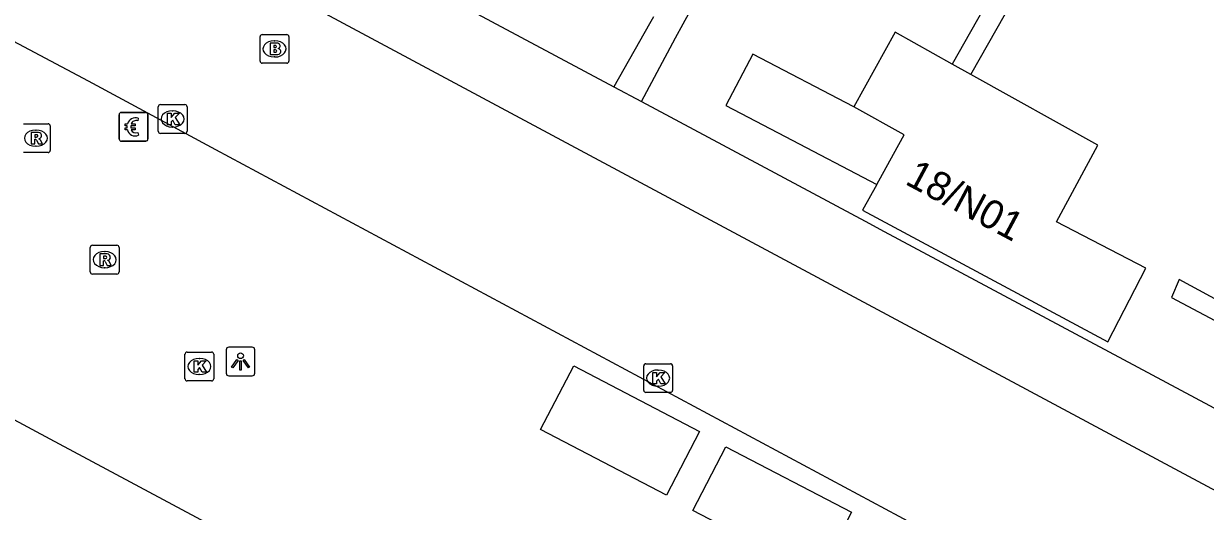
# Model space of a CAD drawing. Extents: x 159489 to 160304, y 383826 to 384530.
# Drawn here: x 160083.44 to 160124.51, y 384041.9 to 384058.85 of the extents above; entities that cross this region are included whole.
import ezdxf

# ---------------------------------------------------------------- set-up
doc = ezdxf.new("R2010")
doc.units = 0
for name, color, linetype in [('IMGEO_Betaalautomaat', 7, 'Continuous'), ('IMGEO_Brandkraan', 7, 'Continuous'), ('IMGEO_Fietspad_gesloten', 7, 'Continuous'), ('IMGEO_Haag', 7, 'Continuous'), ('IMGEO_Kolk', 7, 'Continuous'), ('IMGEO_Lichtpunt', 7, 'Continuous'), ('IMGEO_Pand', 7, 'Continuous'), ('IMGEO_Pand_nummerreeks', 7, 'Continuous'), ('IMGEO_Parkeervlak_open', 7, 'Continuous'), ('IMGEO_Rijbaan_lokaal_open', 7, 'Continuous'), ('IMGEO_Rioolput', 7, 'Continuous'), ('IMGEO_Voetpad_op_trap', 7, 'Continuous'), ('IMGEO_Voetpad_open', 7, 'Continuous')]:
    doc.layers.add(name, color=color, linetype=linetype)

msp = doc.modelspace()

# ---------------------------------------------------------------- linework, layer by layer
at = {"layer": 'IMGEO_Betaalautomaat'}
for p, q in [((160086.762, 384054.84), (160086.762, 384055.681)), ((160086.762, 384055.681), (160086.762, 384054.84)), ((160086.837, 384055.764), (160087.678, 384055.764)), ((160087.678, 384055.764), (160086.837, 384055.764)), ((160087.761, 384055.69), (160087.761, 384054.849)), ((160087.761, 384054.849), (160087.761, 384055.69)), ((160087.045, 384055.228), (160087.045, 384055.296)), ((160087.166, 384055.296), (160087.166, 384055.228)), ((160087.424, 384055.569), (160087.407, 384055.469)), ((160087.411, 384055.063), (160087.433, 384054.976)), ((160087.687, 384054.765), (160086.846, 384054.765)), ((160086.846, 384054.765), (160087.687, 384054.765))]:
    msp.add_line(p, q, dxfattribs=at)
for points in [[(160087.045, 384055.296), (160086.976, 384055.296), (160086.976, 384055.365), (160087.055, 384055.365)], [(160087.05, 384055.159), (160086.976, 384055.159), (160086.976, 384055.228), (160087.045, 384055.228)], [(160087.177, 384055.365), (160087.324, 384055.365), (160087.324, 384055.296), (160087.166, 384055.296)], [(160087.166, 384055.228), (160087.324, 384055.228), (160087.324, 384055.159), (160087.18, 384055.159)]]:
    msp.add_lwpolyline(points, dxfattribs=at)
for centre, radius, start, end in [((160086.84, 384055.687), 0.0779, 92.4484, 184.2845), ((160086.84, 384055.687), 0.0779, 92.4484, 184.2845), ((160087.684, 384055.687), 0.0779, 2.4484, 94.2845), ((160087.684, 384055.687), 0.0779, 2.4484, 94.2845), ((160087.338, 384055.289), 0.293, 73.014, 165.0139), ((160087.344, 384055.302), 0.179, 69.3236, 159.5683), ((160086.84, 384054.843), 0.0779, 182.4484, 274.2845), ((160086.84, 384054.843), 0.0779, 182.4484, 274.2845), ((160087.311, 384055.214), 0.267, 191.8096, 297.0389), ((160087.344, 384055.229), 0.179, 202.7625, 291.8693), ((160087.684, 384054.843), 0.0779, 272.4484, 4.2845), ((160087.684, 384054.843), 0.0779, 272.4484, 4.2845)]:
    msp.add_arc(centre, radius, start, end, dxfattribs=at)
at = {"layer": 'IMGEO_Brandkraan'}
for p, q in [((160091.661, 384057.545), (160091.661, 384058.397)), ((160091.736, 384058.471), (160092.588, 384058.471)), ((160092.149, 384058.251), (160092.174, 384058.251)), ((160092.662, 384058.397), (160092.662, 384057.545)), ((160092.172, 384057.691), (160092.147, 384057.691)), ((160092.588, 384057.471), (160091.736, 384057.471))]:
    msp.add_line(p, q, dxfattribs=at)
for points in [[(160091.661, 384057.545), (160091.661, 384058.397)], [(160091.736, 384058.471), (160092.588, 384058.471)], [(160092.009, 384058.171), (160092.009, 384057.771), (160092.222, 384057.771)], [(160092.24, 384058.171), (160092.009, 384058.171)], [(160092.188, 384058.09), (160092.134, 384058.09), (160092.134, 384058.014)], [(160092.662, 384058.397), (160092.662, 384057.545)], [(160092.134, 384058.014), (160092.187, 384058.014)], [(160092.196, 384057.938), (160092.134, 384057.938), (160092.134, 384057.857)], [(160092.134, 384057.857), (160092.196, 384057.857)], [(160092.588, 384057.471), (160091.736, 384057.471)]]:
    msp.add_lwpolyline(points, dxfattribs=at)
for centre, radius, start, end in [((160091.738, 384058.395), 0.0765, 91.552, 178.448), ((160091.738, 384058.395), 0.0765, 91.552, 178.448), ((160092.189, 384058.052), 0.0379, 267.8285, 90.9355), ((160092.244, 384058.026), 0.145, 59.4692, 91.5367), ((160092.269, 384058.073), 0.0922, 285.5137, 58.1501), ((160092.586, 384058.395), 0.0765, 1.552, 88.448), ((160092.586, 384058.395), 0.0765, 1.552, 88.448), ((160092.197, 384057.897), 0.0404, 269.8759, 90.5077), ((160092.228, 384058.022), 0.251, 268.6676, 293.5347), ((160092.274, 384057.881), 0.105, 301.3115, 78.989), ((160091.738, 384057.547), 0.0765, 181.552, 268.448), ((160091.738, 384057.547), 0.0765, 181.552, 268.448), ((160092.586, 384057.547), 0.0765, 271.552, 358.448), ((160092.586, 384057.547), 0.0765, 271.552, 358.448)]:
    msp.add_arc(centre, radius, start, end, dxfattribs=at)
for centre, major_axis, ratio, start_param, end_param in [((160092.148, 384057.971), (-0.387, 0.002), 0.722429, 4.712389, 7.853982), ((160092.173, 384057.971), (-0.39, 0.002), 0.717154, 1.570796, 4.712389)]:
    msp.add_ellipse(centre, major_axis=major_axis, ratio=ratio, start_param=start_param, end_param=end_param, dxfattribs=at)
at = {"layer": 'IMGEO_Fietspad_gesloten'}
msp.add_arc((160615.404, 384561.74), 696.522, 225.116755, 226.921789, dxfattribs=at)
at = {"layer": 'IMGEO_Haag'}
msp.add_lwpolyline([(160123.601, 384049.959), (160123.333, 384049.339), (160129.56, 384046.03), (160129.855, 384046.571), (160123.601, 384049.959)], dxfattribs=at)
at = {"layer": 'IMGEO_Kolk'}
for p, q in [((160088.196, 384056.036), (160089.048, 384056.036)), ((160088.121, 384055.11), (160088.121, 384055.962)), ((160088.609, 384055.816), (160088.634, 384055.816)), ((160089.122, 384055.962), (160089.122, 384055.11)), ((160088.632, 384055.256), (160088.607, 384055.256)), ((160089.048, 384055.036), (160088.196, 384055.036)), ((160089.126, 384047.437), (160089.978, 384047.437)), ((160089.051, 384046.511), (160089.051, 384047.363)), ((160089.539, 384047.217), (160089.564, 384047.217)), ((160090.052, 384047.363), (160090.052, 384046.511)), ((160105.07, 384047.034), (160105.922, 384047.034)), ((160089.562, 384046.657), (160089.537, 384046.657)), ((160104.995, 384046.108), (160104.995, 384046.96)), ((160105.483, 384046.814), (160105.508, 384046.814)), ((160105.996, 384046.96), (160105.996, 384046.108)), ((160089.978, 384046.437), (160089.126, 384046.437)), ((160105.506, 384046.254), (160105.481, 384046.254)), ((160105.922, 384046.034), (160105.07, 384046.034))]:
    msp.add_line(p, q, dxfattribs=at)
for points in [[(160088.196, 384056.036), (160089.048, 384056.036)], [(160088.121, 384055.11), (160088.121, 384055.962)], [(160088.442, 384055.736), (160088.565, 384055.736), (160088.565, 384055.585), (160088.695, 384055.736), (160088.859, 384055.736), (160088.713, 384055.585), (160088.866, 384055.336), (160088.714, 384055.336), (160088.629, 384055.5), (160088.565, 384055.433), (160088.565, 384055.336), (160088.442, 384055.336), (160088.442, 384055.736)], [(160089.122, 384055.962), (160089.122, 384055.11)], [(160089.048, 384055.036), (160088.196, 384055.036)], [(160089.126, 384047.437), (160089.978, 384047.437)], [(160089.051, 384046.511), (160089.051, 384047.363)], [(160089.372, 384047.137), (160089.495, 384047.137), (160089.495, 384046.986), (160089.625, 384047.137), (160089.789, 384047.137), (160089.643, 384046.986), (160089.796, 384046.737), (160089.644, 384046.737), (160089.559, 384046.901), (160089.495, 384046.834), (160089.495, 384046.737), (160089.372, 384046.737), (160089.372, 384047.137)], [(160090.052, 384047.363), (160090.052, 384046.511)], [(160105.07, 384047.034), (160105.922, 384047.034)], [(160104.995, 384046.108), (160104.995, 384046.96)], [(160105.316, 384046.734), (160105.439, 384046.734), (160105.439, 384046.583), (160105.569, 384046.734), (160105.733, 384046.734), (160105.587, 384046.583), (160105.74, 384046.334), (160105.588, 384046.334), (160105.503, 384046.498), (160105.439, 384046.431), (160105.439, 384046.334), (160105.316, 384046.334), (160105.316, 384046.734)], [(160105.996, 384046.96), (160105.996, 384046.108)], [(160089.978, 384046.437), (160089.126, 384046.437)], [(160105.922, 384046.034), (160105.07, 384046.034)]]:
    msp.add_lwpolyline(points, dxfattribs=at)
for centre, start, end in [((160088.198, 384055.96), 91.552, 178.448), ((160088.198, 384055.96), 91.552, 178.448), ((160089.046, 384055.96), 1.552, 88.448), ((160089.046, 384055.96), 1.552, 88.448), ((160088.198, 384055.112), 181.552, 268.448), ((160088.198, 384055.112), 181.552, 268.448), ((160089.046, 384055.112), 271.552, 358.448), ((160089.046, 384055.112), 271.552, 358.448), ((160089.128, 384047.361), 91.552, 178.448), ((160089.128, 384047.361), 91.552, 178.448), ((160089.976, 384047.361), 1.552, 88.448), ((160089.976, 384047.361), 1.552, 88.448), ((160105.072, 384046.958), 91.552, 178.448), ((160105.072, 384046.958), 91.552, 178.448), ((160105.92, 384046.958), 1.552, 88.448), ((160105.92, 384046.958), 1.552, 88.448), ((160089.128, 384046.513), 181.552, 268.448), ((160089.128, 384046.513), 181.552, 268.448), ((160089.976, 384046.513), 271.552, 358.448), ((160089.976, 384046.513), 271.552, 358.448), ((160105.072, 384046.11), 181.552, 268.448), ((160105.072, 384046.11), 181.552, 268.448), ((160105.92, 384046.11), 271.552, 358.448), ((160105.92, 384046.11), 271.552, 358.448)]:
    msp.add_arc(centre, 0.0765, start, end, dxfattribs=at)
for centre, major_axis, ratio, start_param, end_param in [((160088.608, 384055.536), (-0.387, 0.002), 0.722429, 4.712389, 7.853982), ((160088.633, 384055.536), (-0.39, 0.002), 0.717154, 1.570796, 4.712389), ((160089.538, 384046.937), (-0.387, 0.002), 0.722429, 4.712389, 7.853982), ((160089.563, 384046.937), (-0.39, 0.002), 0.717154, 1.570796, 4.712389), ((160105.482, 384046.534), (-0.387, 0.002), 0.722429, 4.712389, 7.853982), ((160105.507, 384046.534), (-0.39, 0.002), 0.717154, 1.570796, 4.712389)]:
    msp.add_ellipse(centre, major_axis=major_axis, ratio=ratio, start_param=start_param, end_param=end_param, dxfattribs=at)
at = {"layer": 'IMGEO_Lichtpunt'}
for p, q in [((160090.483, 384047.514), (160090.483, 384046.707)), ((160090.483, 384047.514), (160090.483, 384046.707)), ((160091.385, 384047.609), (160090.577, 384047.609)), ((160091.385, 384047.609), (160090.577, 384047.609)), ((160091.479, 384046.707), (160091.479, 384047.514)), ((160091.479, 384046.707), (160091.479, 384047.514)), ((160090.577, 384046.613), (160091.385, 384046.613)), ((160090.577, 384046.613), (160091.385, 384046.613))]:
    msp.add_line(p, q, dxfattribs=at)
for points in [[(160090.857, 384047.178), (160090.896, 384047.15), (160090.708, 384046.888), (160090.67, 384046.915), (160090.857, 384047.178)], [(160090.959, 384047.13), (160091.006, 384047.13), (160091.006, 384046.808), (160090.959, 384046.808), (160090.959, 384047.13)], [(160091.069, 384047.15), (160091.107, 384047.177), (160091.294, 384046.915), (160091.255, 384046.887), (160091.069, 384047.15)]]:
    msp.add_lwpolyline(points, dxfattribs=at)
msp.add_circle((160090.982, 384047.312), 0.0994, dxfattribs=at)
for centre, start, end in [((160090.577, 384047.514), 90, 180), ((160090.577, 384047.514), 90, 180), ((160091.385, 384047.514), 0, 90), ((160091.385, 384047.514), 0, 90), ((160090.577, 384046.707), 180, 270), ((160090.577, 384046.707), 180, 270), ((160091.385, 384046.707), 270, 0), ((160091.385, 384046.707), 270, 360)]:
    msp.add_arc(centre, 0.0946, start, end, dxfattribs=at)
at = {"layer": 'IMGEO_Pand'}
for points in [[(160073.755, 384058.611), (160074.776, 384058.065), (160074.653, 384057.835), (160074.445, 384057.447), (160075.061, 384057.116), (160072.374, 384052.088), (160071.43, 384052.592), (160070.91, 384051.621), (160077.333, 384048.184), (160084.358, 384044.424), (160120.106, 384025.292)], [(160115.714, 384057.446), (160113.731, 384058.549), (160112.297, 384055.958)], [(160116.369, 384057.081), (160115.714, 384057.446)], [(160113.091, 384053.263), (160112.594, 384052.365), (160121.127, 384047.794), (160122.451, 384050.357), (160119.343, 384051.962), (160120.775, 384054.629), (160116.369, 384057.081)], [(160113.091, 384053.263), (160113.67, 384054.308), (160114.047, 384054.99), (160112.297, 384055.958)]]:
    msp.add_lwpolyline(points, dxfattribs=at)
at = {"layer": 'IMGEO_Parkeervlak_open'}
for points in [[(160098.684, 384059.472), (160103.951, 384056.655)], [(160104.914, 384056.141), (160112.692, 384051.981), (160113.354, 384051.627), (160128.32, 384043.623)]]:
    msp.add_lwpolyline(points, dxfattribs=at)
at = {"layer": 'IMGEO_Rijbaan_lokaal_open'}
for points in [[(160171.245, 384010.937), (160125.267, 384035.607), (160090.12, 384054.464), (160085.703, 384056.846), (160076.546, 384061.719), (160076.371, 384061.813)], [(160131.209, 384039.227), (160093.439, 384059.454)]]:
    msp.add_lwpolyline(points, dxfattribs=at)
at = {"layer": 'IMGEO_Rioolput'}
for p, q in [((160083.443, 384055.369), (160084.295, 384055.369)), ((160084.369, 384055.295), (160084.369, 384054.443)), ((160083.856, 384055.149), (160083.881, 384055.149)), ((160083.879, 384054.589), (160083.854, 384054.589)), ((160084.295, 384054.369), (160083.443, 384054.369)), ((160085.835, 384051.149), (160086.687, 384051.149)), ((160085.76, 384050.223), (160085.76, 384051.075)), ((160086.248, 384050.929), (160086.273, 384050.929)), ((160086.761, 384051.075), (160086.761, 384050.223)), ((160086.271, 384050.369), (160086.246, 384050.369)), ((160086.687, 384050.149), (160085.835, 384050.149))]:
    msp.add_line(p, q, dxfattribs=at)
for points in [[(160083.443, 384055.369), (160084.295, 384055.369)], [(160084.369, 384055.295), (160084.369, 384054.443)], [(160083.957, 384055.067), (160083.705, 384055.069), (160083.705, 384054.669)], [(160083.705, 384054.669), (160083.829, 384054.669), (160083.829, 384054.831), (160083.84, 384054.831)], [(160083.883, 384054.988), (160083.829, 384054.988), (160083.829, 384054.907)], [(160083.829, 384054.907), (160083.881, 384054.907)], [(160083.887, 384054.802), (160083.958, 384054.669), (160084.098, 384054.669), (160084.033, 384054.795)], [(160084.295, 384054.369), (160083.443, 384054.369)], [(160085.835, 384051.149), (160086.687, 384051.149)], [(160085.76, 384050.223), (160085.76, 384051.075)], [(160086.349, 384050.847), (160086.097, 384050.849), (160086.097, 384050.449)], [(160086.275, 384050.768), (160086.221, 384050.768), (160086.221, 384050.687)], [(160086.221, 384050.687), (160086.273, 384050.687)], [(160086.761, 384051.075), (160086.761, 384050.223)], [(160086.097, 384050.449), (160086.221, 384050.449), (160086.221, 384050.611), (160086.232, 384050.611)], [(160086.279, 384050.582), (160086.35, 384050.449), (160086.49, 384050.449), (160086.425, 384050.575)], [(160086.687, 384050.149), (160085.835, 384050.149)]]:
    msp.add_lwpolyline(points, dxfattribs=at)
for centre, radius, start, end in [((160084.293, 384055.293), 0.0765, 1.552, 88.448), ((160084.293, 384055.293), 0.0765, 1.552, 88.448), ((160083.839, 384054.778), 0.0533, 26.0293, 88.6989), ((160083.865, 384055.096), 0.19, 274.7715, 282.9687), ((160083.889, 384054.892), 0.0964, 77.0061, 93.1865), ((160083.903, 384054.949), 0.0378, 276.6634, 79.6772), ((160083.956, 384054.957), 0.109, 350.3612, 89.416), ((160083.954, 384054.957), 0.112, 277.5842, 350.9817), ((160083.938, 384054.742), 0.108, 29.5134, 73.7905), ((160084.293, 384054.445), 0.0765, 271.552, 358.448), ((160084.293, 384054.445), 0.0765, 271.552, 358.448), ((160085.837, 384051.073), 0.0765, 91.552, 178.448), ((160085.837, 384051.073), 0.0765, 91.552, 178.448), ((160086.685, 384051.073), 0.0765, 1.552, 88.448), ((160086.685, 384051.073), 0.0765, 1.552, 88.448), ((160086.257, 384050.876), 0.19, 274.7715, 282.9687), ((160086.281, 384050.672), 0.0964, 77.0061, 93.1865), ((160086.295, 384050.729), 0.0378, 276.6634, 79.6772), ((160086.348, 384050.737), 0.109, 350.3612, 89.416), ((160086.346, 384050.737), 0.112, 277.5842, 350.9817), ((160086.231, 384050.558), 0.0533, 26.0293, 88.6989), ((160086.33, 384050.522), 0.108, 29.5134, 73.7905), ((160085.837, 384050.225), 0.0765, 181.552, 268.448), ((160085.837, 384050.225), 0.0765, 181.552, 268.448), ((160086.685, 384050.225), 0.0765, 271.552, 358.448), ((160086.685, 384050.225), 0.0765, 271.552, 358.448)]:
    msp.add_arc(centre, radius, start, end, dxfattribs=at)
for centre, major_axis, ratio, start_param, end_param in [((160083.855, 384054.869), (-0.387, 0.002), 0.722429, 4.712389, 7.853982), ((160083.88, 384054.869), (-0.39, 0.002), 0.717154, 1.570796, 4.712389), ((160086.247, 384050.649), (-0.387, 0.002), 0.722429, 4.712389, 7.853982), ((160086.272, 384050.649), (-0.39, 0.002), 0.717154, 1.570796, 4.712389)]:
    msp.add_ellipse(centre, major_axis=major_axis, ratio=ratio, start_param=start_param, end_param=end_param, dxfattribs=at)
at = {"layer": 'IMGEO_Voetpad_op_trap'}
msp.add_lwpolyline([(160112.297, 384055.958), (160108.792, 384057.792), (160107.843, 384056.009), (160109.91, 384054.931), (160113.091, 384053.263)], dxfattribs=at)
at = {"layer": 'IMGEO_Voetpad_open'}
for points in [[(160104.914, 384056.141), (160106.095, 384058.358), (160106.36, 384058.84), (160109.265, 384064.12), (160109.584, 384063.95), (160109.093, 384063.095), (160109.443, 384062.901), (160109.792, 384063.474), (160110.171, 384063.288), (160110.632, 384064.203), (160111.391, 384063.742), (160111.934, 384064.739), (160111.599, 384064.94), (160111.949, 384065.564), (160111.562, 384065.743), (160111.345, 384065.376), (160110.979, 384065.594), (160110.61, 384064.917), (160110.246, 384065.133), (160111.324, 384067.09), (160111, 384067.274), (160114.745, 384074.082)], [(160121.404, 384067.481), (160115.714, 384057.446)], [(160116.369, 384057.081), (160121.956, 384066.933)], [(160105.336, 384059.086), (160105.195, 384058.839), (160103.951, 384056.655)], [(160103.951, 384056.655), (160104.914, 384056.141)], [(160101.411, 384044.746), (160102.561, 384046.957), (160106.931, 384044.683), (160105.781, 384042.472), (160101.411, 384044.746)], [(160106.698, 384041.938), (160107.848, 384044.149), (160112.218, 384041.875), (160111.067, 384039.664), (160106.698, 384041.938)]]:
    msp.add_lwpolyline(points, dxfattribs=at)

# ---------------------------------------------------------------- texts
at = {"layer": 'IMGEO_Pand_nummerreeks'}
msp.add_text('18/N01', height=1, rotation=331.8219, dxfattribs=at).set_placement((160114.038, 384053.293))

doc.saveas('drawing.dxf')
